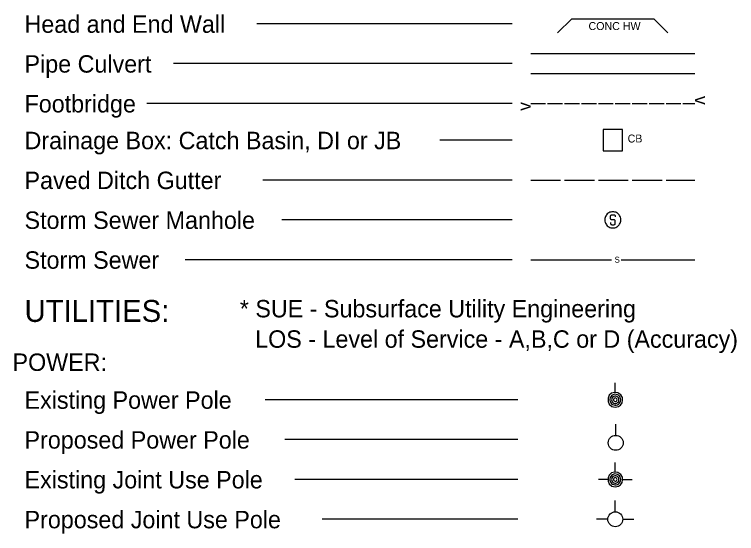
# Model space of a CAD drawing. Extents: x 0 to 3, y 0 to 1.83.
# Drawn here: x 1.471 to 2.081, y 0.931 to 1.369 of the extents above; entities that cross this region are included whole.
import ezdxf

# ---------------------------------------------------------------- set-up
doc = ezdxf.new("R2010")
doc.units = 0
doc.layers.add('Sheet_Symbology', color=7, linetype='Continuous')

msp = doc.modelspace()

# ---------------------------------------------------------------- linework, layer by layer
at = {"layer": 'Sheet_Symbology'}
for p, q in [((1.89175, 1.36117), (1.676, 1.36117)), ((1.93017, 1.35348), (1.94207, 1.36537)), ((1.94207, 1.36537), (2.01143, 1.36537)), ((2.01143, 1.36537), (2.02333, 1.35348)), ((1.90739, 1.33595), (2.04611, 1.33595)), ((1.89175, 1.32754), (1.60557, 1.32754)), ((1.90739, 1.31913), (2.04611, 1.31913)), ((1.89175, 1.29391), (1.58322, 1.29391)), ((1.90739, 1.29391), (1.92, 1.29391)), ((1.92168, 1.29391), (1.93429, 1.29391)), ((1.93597, 1.29391), (1.94858, 1.29391)), ((1.95027, 1.29391), (1.96288, 1.29391)), ((1.96456, 1.29391), (1.97717, 1.29391)), ((1.97885, 1.29391), (1.99146, 1.29391)), ((1.99315, 1.29391), (2.00576, 1.29391)), ((2.00744, 1.29391), (2.02005, 1.29391)), ((2.02173, 1.29391), (2.03434, 1.29391)), ((2.03603, 1.29391), (2.04611, 1.29391)), ((1.89175, 1.2629), (1.83072, 1.2629)), ((1.89175, 1.22927), (1.68124, 1.22927)), ((1.90739, 1.22927), (1.93261, 1.22927)), ((1.93597, 1.22927), (1.9612, 1.22927)), ((1.96456, 1.22927), (1.98978, 1.22927)), ((1.99315, 1.22927), (2.01837, 1.22927)), ((2.02173, 1.22927), (2.04611, 1.22927)), ((1.89175, 1.19564), (1.69723, 1.19564)), ((1.97473, 1.19684), (1.97473, 1.19865)), ((1.97593, 1.19985), (1.97773, 1.19985)), ((1.97773, 1.1957), (1.97593, 1.1957)), ((1.97888, 1.19865), (1.97888, 1.19805)), ((1.97473, 1.19329), (1.97473, 1.19269)), ((1.97593, 1.19155), (1.97773, 1.19155)), ((1.97888, 1.19269), (1.97888, 1.19455)), ((1.89175, 1.16201), (1.61563, 1.16201)), ((1.90739, 1.16201), (1.97553, 1.16201)), ((1.98394, 1.16201), (2.04611, 1.16201)), ((1.97885, 1.05), (1.97885, 1.05807)), ((1.89643, 1.04379), (1.6831, 1.04379)), ((1.97921, 1.01371), (1.97921, 1.02317)), ((1.89643, 1.01016), (1.69972, 1.01016)), ((1.97885, 0.98274), (1.97885, 0.99081)), ((1.89643, 0.97653), (1.70825, 0.97653)), ((1.97264, 0.97653), (1.96458, 0.97653)), ((1.98506, 0.97653), (1.99313, 0.97653)), ((1.97885, 0.94923), (1.97885, 0.95869)), ((1.89643, 0.9429), (1.73126, 0.9429)), ((1.97255, 0.94292), (1.96309, 0.94292)), ((1.98516, 0.94292), (1.99462, 0.94292))]:
    msp.add_line(p, q, dxfattribs=at)
for points in [[(1.96866, 1.25397), (1.98482, 1.25397), (1.98482, 1.27186), (1.96866, 1.27186)], [(1.97885, 1.03759), (1.98146, 1.03808), (1.9832, 1.03932), (1.98456, 1.04106), (1.98506, 1.04342), (1.98481, 1.04566), (1.98357, 1.04789), (1.98109, 1.04975), (1.97823, 1.05), (1.97575, 1.04925), (1.97376, 1.04752), (1.97277, 1.04516), (1.97277, 1.04243), (1.97376, 1.04007), (1.976, 1.0382)], [(1.97885, 0.97032), (1.98146, 0.97082), (1.9832, 0.97206), (1.98456, 0.9738), (1.98506, 0.97616), (1.98481, 0.97839), (1.98357, 0.98063), (1.98109, 0.98249), (1.97823, 0.98274), (1.97575, 0.98199), (1.97376, 0.98025), (1.97277, 0.9779), (1.97277, 0.97516), (1.97376, 0.97281), (1.976, 0.97094)]]:
    msp.add_lwpolyline(points, close=True, dxfattribs=at)
for points in [[(1.97675, 1.20247), (1.97588, 1.20241), (1.97506, 1.20225), (1.97424, 1.20198), (1.97347, 1.20159), (1.97276, 1.20116), (1.97211, 1.20061), (1.97151, 1.19996), (1.97101, 1.1993), (1.97058, 1.19854), (1.97031, 1.19772), (1.97009, 1.1969), (1.96998, 1.19608), (1.96998, 1.19521), (1.97009, 1.19439), (1.97031, 1.19351), (1.97058, 1.19275), (1.97101, 1.19198), (1.97151, 1.19133), (1.97211, 1.19067), (1.97276, 1.19013), (1.97347, 1.18969), (1.97424, 1.18931), (1.97506, 1.18903), (1.97593, 1.18887), (1.97675, 1.18882), (1.97762, 1.18887), (1.97844, 1.18903), (1.97926, 1.18931), (1.98003, 1.18969), (1.98074, 1.19013), (1.98139, 1.19067), (1.982, 1.19133), (1.98249, 1.19198), (1.98292, 1.19275), (1.9832, 1.19357), (1.98341, 1.19439), (1.98352, 1.19521), (1.98352, 1.19608), (1.98341, 1.1969), (1.9832, 1.19777), (1.98292, 1.19854), (1.98249, 1.1993), (1.982, 1.19996), (1.98139, 1.20061), (1.98074, 1.20116), (1.98003, 1.20159), (1.97926, 1.20198), (1.97844, 1.20225), (1.97757, 1.20241), (1.97675, 1.20247)], [(1.97473, 1.19865), (1.97484, 1.19903), (1.975, 1.19936), (1.97522, 1.19957), (1.97555, 1.19974), (1.97593, 1.19985)], [(1.97593, 1.1957), (1.97555, 1.19575), (1.97522, 1.19591), (1.975, 1.19619), (1.97484, 1.19652), (1.97473, 1.19684)], [(1.97773, 1.19985), (1.97806, 1.19974), (1.97839, 1.19957), (1.97866, 1.19936), (1.97883, 1.19903), (1.97888, 1.19865)], [(1.97888, 1.1945), (1.97883, 1.19488), (1.97866, 1.19521), (1.97839, 1.19548), (1.97806, 1.19564), (1.97773, 1.1957)], [(1.97473, 1.19275), (1.97484, 1.19237), (1.975, 1.19204), (1.97522, 1.19176), (1.97555, 1.1916), (1.97593, 1.19155)], [(1.97773, 1.19155), (1.97806, 1.1916), (1.97839, 1.19176), (1.97866, 1.19204), (1.97883, 1.19237), (1.97888, 1.19275)], [(1.98345, 1.04379), (1.98332, 1.04491), (1.98295, 1.0459), (1.98233, 1.04677), (1.98158, 1.04752), (1.98072, 1.04802), (1.9796, 1.04826), (1.9786, 1.04839), (1.97749, 1.04814), (1.97649, 1.04777), (1.97575, 1.04715), (1.97501, 1.04628), (1.97451, 1.04541), (1.97426, 1.04429), (1.97426, 1.0433), (1.97451, 1.04218), (1.97501, 1.04131), (1.97575, 1.04044), (1.97649, 1.03982), (1.97749, 1.03945), (1.9786, 1.0392), (1.9796, 1.03932), (1.98072, 1.03957), (1.98158, 1.04007), (1.98233, 1.04081), (1.98295, 1.04168), (1.98332, 1.04268), (1.98345, 1.04379)], [(1.98195, 1.04379), (1.98183, 1.04466), (1.98146, 1.04553), (1.98084, 1.04615), (1.9801, 1.04665), (1.97935, 1.0469), (1.97836, 1.0469), (1.97761, 1.04665), (1.97687, 1.04615), (1.97625, 1.04553), (1.97587, 1.04466), (1.97575, 1.04379), (1.97587, 1.04292), (1.97625, 1.04206), (1.97687, 1.04143), (1.97761, 1.04094), (1.97836, 1.04069), (1.97935, 1.04069), (1.9801, 1.04094), (1.98084, 1.04143), (1.98146, 1.04206), (1.98183, 1.04292), (1.98195, 1.04379)], [(1.98034, 1.04379), (1.98022, 1.04441), (1.97985, 1.04491), (1.97935, 1.04516), (1.97873, 1.04528), (1.97811, 1.04504), (1.97761, 1.04466), (1.97736, 1.04404), (1.97736, 1.04354), (1.97761, 1.04292), (1.97811, 1.04255), (1.97873, 1.0423), (1.97935, 1.04243), (1.97985, 1.04268), (1.98022, 1.04317), (1.98034, 1.04379)], [(1.98345, 0.97653), (1.98332, 0.97765), (1.98295, 0.97864), (1.98233, 0.97951), (1.98158, 0.98025), (1.98072, 0.98075), (1.9796, 0.981), (1.9786, 0.98113), (1.97749, 0.98088), (1.97649, 0.9805), (1.97575, 0.97988), (1.97501, 0.97901), (1.97451, 0.97814), (1.97426, 0.97703), (1.97426, 0.97603), (1.97451, 0.97492), (1.97501, 0.97405), (1.97575, 0.97318), (1.97649, 0.97256), (1.97749, 0.97219), (1.9786, 0.97194), (1.9796, 0.97206), (1.98072, 0.97231), (1.98158, 0.97281), (1.98233, 0.97355), (1.98295, 0.97442), (1.98332, 0.97541), (1.98345, 0.97653)], [(1.98195, 0.97653), (1.98183, 0.9774), (1.98146, 0.97827), (1.98084, 0.97889), (1.9801, 0.97939), (1.97935, 0.97963), (1.97836, 0.97963), (1.97761, 0.97939), (1.97687, 0.97889), (1.97625, 0.97827), (1.97587, 0.9774), (1.97575, 0.97653), (1.97587, 0.97566), (1.97625, 0.97479), (1.97687, 0.97417), (1.97761, 0.97367), (1.97836, 0.97343), (1.97935, 0.97343), (1.9801, 0.97367), (1.98084, 0.97417), (1.98146, 0.97479), (1.98183, 0.97566), (1.98195, 0.97653)], [(1.98034, 0.97653), (1.98022, 0.97715), (1.97985, 0.97765), (1.97935, 0.9779), (1.97873, 0.97802), (1.97811, 0.97777), (1.97761, 0.9774), (1.97736, 0.97678), (1.97736, 0.97628), (1.97761, 0.97566), (1.97811, 0.97529), (1.97873, 0.97504), (1.97935, 0.97516), (1.97985, 0.97541), (1.98022, 0.97591), (1.98034, 0.97653)]]:
    msp.add_lwpolyline(points, dxfattribs=at)
for centre in [(1.97921, 1.00741), (1.97885, 0.9429)]:
    msp.add_circle(centre, 0.00631, dxfattribs=at)

# ---------------------------------------------------------------- texts
for s, height, p in [('Head and End Wall', 0.0147137, (1.47983, 1.35352)), ('CONC HW', 0.006726, (1.95624, 1.35585)), ('Pipe Culvert', 0.0147137, (1.47983, 1.31991)), ('Footbridge', 0.014714, (1.47985, 1.28628)), ('Drainage Box: Catch Basin, DI or JB', 0.0147137, (1.47985, 1.25527)), ('CB', 0.006726, (1.98926, 1.26093)), ('Paved Ditch Gutter', 0.0147137, (1.47985, 1.22162)), ('Storm Sewer Manhole', 0.0147137, (1.47985, 1.18799)), ('Storm Sewer', 0.0147137, (1.47985, 1.15436)), ('S', 0.00504, (1.97822, 1.15949)), ('* SUE - Subsurface Utility Engineering', 0.0147137, (1.6617, 1.11329)), ('UTILITIES:', 0.018497, (1.47983, 1.10949)), ('LOS - Level of Service - A,B,C or D (Accuracy) ', 0.0147137, (1.67467, 1.08766)), ('POWER:', 0.014714, (1.4697, 1.06811)), ('Existing Power Pole', 0.0147137, (1.47985, 1.03616)), ('Proposed Power Pole', 0.0147137, (1.47985, 1.00253)), ('Existing Joint Use Pole', 0.0147137, (1.47985, 0.96892)), ('Proposed Joint Use Pole', 0.0147137, (1.47987, 0.93527))]:
    msp.add_text(s, height=height, dxfattribs=at).set_placement(p)
for rotation, p in [(270.24085, (2.04609, 1.30019)), (89.75915, (1.90736, 1.28762))]:
    msp.add_text('v', height=0.0111, rotation=rotation, dxfattribs=at).set_placement(p)

doc.saveas('drawing.dxf')
